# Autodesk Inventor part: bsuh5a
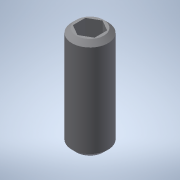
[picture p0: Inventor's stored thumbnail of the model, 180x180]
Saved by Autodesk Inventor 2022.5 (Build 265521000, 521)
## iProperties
Created: 2016-12
Part Number: bsuh5a
Material: 一般
Document SubType Name: Modeling
Designer: imaocorp
Density: 1 g/cm^3
Appearance: 既定
Author: imaocorp
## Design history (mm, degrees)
node "bsuh5a.x_t1"
node "bsuh5a"
node "Base1"
